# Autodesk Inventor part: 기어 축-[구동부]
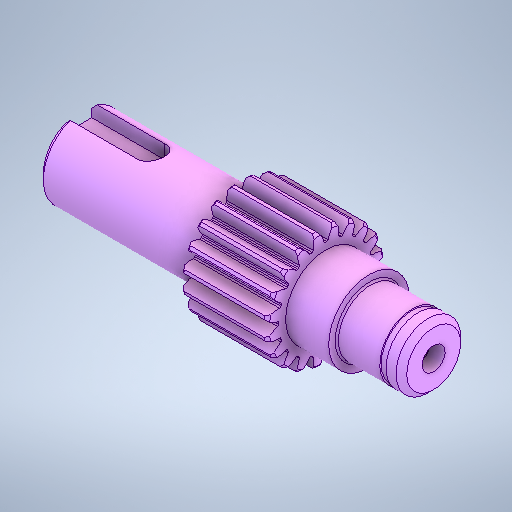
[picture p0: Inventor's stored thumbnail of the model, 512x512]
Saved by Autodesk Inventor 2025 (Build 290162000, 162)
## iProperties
Created: 2026-07
Part Number: 기어 축-[구동부]
Material: 강철, 합금
Document SubType Name: Modeling
Designer: KDI
Density: 7.73 g/cm^3
Appearance: 반연마
Mass: 98.31 g
Surface Area: 48.6737 cm^2
Volume: 12.718 cm^3
Sending System: Autodesk Inventor 2027
Preprocessor: ST-DEVELOPER v20.1
Author: jhkim
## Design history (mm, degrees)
feature "솔리드1"
node "솔리드2"
